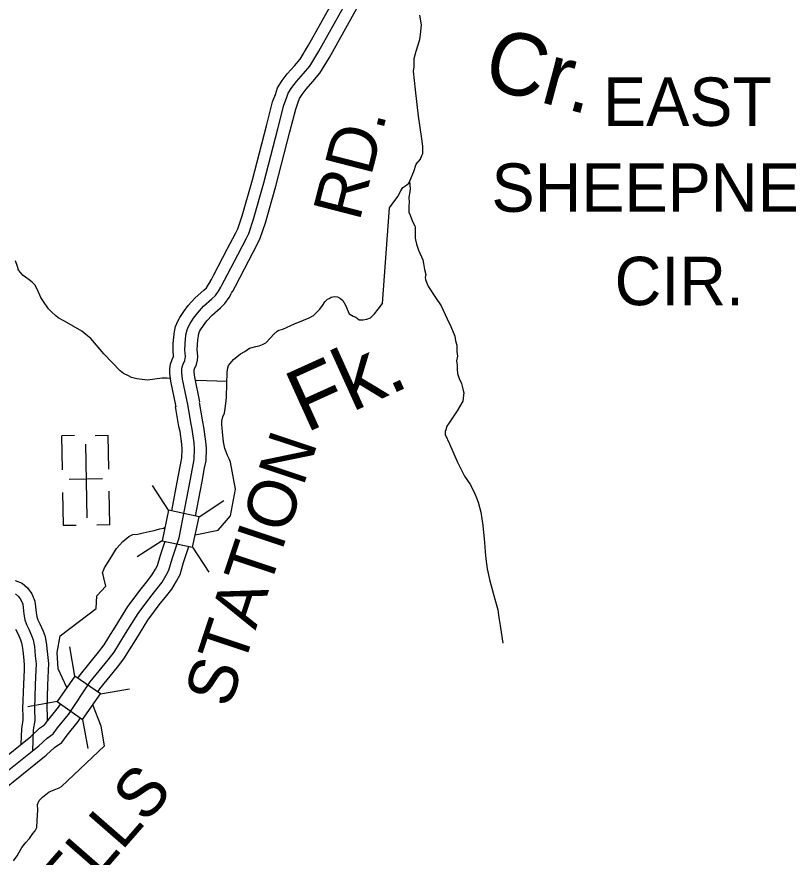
# Model space of a CAD drawing. Extents: x 1551132 to 1791609, y 378168 to 563823.
# Drawn here: x 1676283 to 1682181, y 408888 to 415309 of the extents above; entities that cross this region are included whole.
import ezdxf

# ---------------------------------------------------------------- set-up
doc = ezdxf.new("R2010")
doc.units = 0
for name, color, linetype in [('DESIGN - DRAINAGE - Bridges and Cross Drains Size Text', 7, 'Continuous'), ('DESIGN - ROW - Right-of-Way and Easement Labels', 7, 'Continuous'), ('DESIGN - TRANSPORTATION - Text', 7, 'Continuous'), ('DESIGN - UTILITIES - Cable (Underground) with Text', 7, 'Continuous'), ('SURVEY - DRAINAGE - Storm Sewer', 7, 'Continuous'), ('SURVEY - PROPERTY - Owners', 7, 'Continuous')]:
    doc.layers.add(name, color=color, linetype=linetype)

msp = doc.modelspace()

# ---------------------------------------------------------------- linework, layer by layer
at = {"layer": 'DESIGN - TRANSPORTATION - Text'}
for points in [[(1679132.129, 413849.758), (1679153.645, 413877.808), (1679196.303, 413935.402), (1679218.794, 413979.211), (1679233.085, 414005.078), (1679265.326, 414024.737), (1679279.484, 414038.596), (1679289.734, 414060.505), (1679318.467, 414126.273), (1679337.099, 414184.141), (1679369.532, 414221.826), (1679379.849, 414249.752), (1679386.023, 414265.702), (1679388.24, 414285.703), (1679386.623, 414321.778), (1679377.39, 414393.997), (1679353.049, 414550.526), (1679331.183, 414751.09), (1679316.7, 414893.477), (1679321.067, 414927.478), (1679319.734, 414989.588), (1679336.35, 415045.481), (1679363.341, 415135.308), (1679369.749, 415173.293), (1679376.549, 415247.328), (1679363.341, 415321.596)], [(1679286.092, 414052.721), (1679290.767, 413995.07), (1679286.492, 413971.094), (1679280.026, 413931.118), (1679281.534, 413889.042), (1679281.251, 413865.016), (1679280.859, 413830.982), (1679280.692, 413816.965), (1679290.417, 413792.815), (1679307.858, 413744.53), (1679325.491, 413712.271), (1679327.374, 413702.237), (1679328.958, 413666.17), (1679328.391, 413618.11), (1679332.258, 413606.051), (1679337.857, 413571.934), (1679353.324, 413525.683), (1679386.498, 413453.181), (1679392.148, 413423.071), (1679399.631, 413378.92), (1679409.197, 413340.753), (1679404.914, 413316.777), (1679408.747, 413302.71), (1679418.422, 413274.551), (1679430.105, 413246.375), (1679483.154, 413163.615), (1679528.444, 413100.971), (1679573.31, 413002.286), (1679600.634, 412943.876), (1679631.784, 412869.39), (1679637.367, 412833.281), (1679646.992, 412801.114), (1679646.408, 412751.054), (1679652.016, 412716.945), (1679645.592, 412680.977), (1679649.2, 412646.885), (1679650.85, 412616.825), (1679652.475, 412584.766), (1679666.033, 412546.549), (1679681.574, 412506.306), (1679693.107, 412466.113), (1679694.965, 412454.071), (1679700.757, 412435.979), (1679698.548, 412417.979), (1679694.015, 412371.977), (1679649.141, 412298.434), (1679608.409, 412236.857), (1679588.059, 412207.065), (1679569.751, 412181.256), (1679563.418, 412153.297), (1679557.277, 412141.363), (1679557.002, 412117.329), (1679590.192, 412046.827), (1679650.641, 411911.907), (1679705.348, 411799.087), (1679750.589, 411732.444), (1679783.796, 411663.942), (1679797.454, 411633.733), (1679811.054, 411599.524), (1679830.195, 411525.188), (1679847.011, 411422.844), (1679857.503, 411292.549), (1679862.661, 411220.389), (1679870.061, 411168.229), (1679879.169, 411092.019), (1679896.218, 411009.7), (1679925.009, 410905.206), (1679959.525, 410776.61), (1679968.85, 410718.426), (1679978.158, 410658.232), (1679998.599, 410523.804)], [(1677856.466, 412136.004), (1677853.95, 412165.521), (1677850.267, 412195.605), (1677850.525, 412219.639), (1677858.9, 412253.598), (1677871.183, 412279.491), (1677875.574, 412315.5), (1677882.008, 412355.484), (1677886.491, 412399.502), (1677889.649, 412507.63), (1677890.508, 412587.74), (1677892.833, 412617.766), (1677901.141, 412645.709), (1677939.665, 412691.327), (1677994.164, 412732.761), (1678026.404, 412752.412), (1678062.687, 412776.029), (1678110.877, 412789.488), (1678134.96, 412795.213), (1678161.085, 412804.921), (1678187.259, 412818.638), (1678221.692, 412856.298), (1678248.016, 412884.032), (1678272.265, 412905.782), (1678286.39, 412915.633), (1678316.498, 412923.291), (1678407.021, 412964.301), (1678475.369, 412991.543), (1678517.593, 413009.085), (1678551.817, 413026.711), (1678600.391, 413076.22), (1678620.691, 413102.021), (1678636.999, 413129.88), (1678659.256, 413151.647), (1678671.331, 413157.522), (1678687.448, 413167.348), (1678711.514, 413171.073), (1678735.505, 413168.789), (1678757.396, 413156.514), (1678775.254, 413142.28), (1678794.887, 413105.996), (1678824.194, 413039.553), (1678854.027, 413021.177), (1678875.96, 413012.91), (1678899.759, 412992.602), (1678931.808, 412994.227), (1678959.874, 412997.91), (1678986.024, 413009.619), (1679016.365, 413039.311), (1679044.781, 413075.037), (1679078.497, 413118.997), (1679132.129, 413849.758)], [(1677456.051, 412544.456), (1677429.293, 412548.139), (1677393.286, 412548.581), (1677283.055, 412531.922), (1677201.157, 412542.939), (1677159.258, 412553.473), (1677137.4, 412565.756), (1677097.601, 412584.273), (1677071.827, 412604.615), (1676949.296, 412734.302), (1676848.632, 412851.697), (1676810.966, 412882.198), (1676779.242, 412906.623), (1676646.079, 412982.367), (1676598.371, 413008.984), (1676580.53, 413023.226), (1676546.881, 413053.677), (1676525.156, 413077.978), (1676487.774, 413132.512), (1676466.141, 413164.822), (1676440.817, 413223.206), (1676419.251, 413261.524), (1676399.484, 413281.8), (1676377.685, 413300.092), (1676347.894, 413318.484), (1676330.053, 413332.718), (1676296.512, 413373.185), (1676288.837, 413401.319), (1676273.321, 413443.562)], [(1677889.816, 412522.939), (1677655.271, 412529.039)], [(1677646.663, 411351.541), (1677821.1, 411385.667), (1677916.215, 411495.07), (1677954.256, 411699.617), (1677916.215, 411906.539), (1677905.49, 411932.557), (1677893.74, 411956.732), (1677884.032, 411984.891), (1677874.308, 412011.042), (1677862.833, 412061.252), (1677856.466, 412136.004)], [(1676666.077, 410184.977), (1676600.12, 410327.247), (1676590.612, 410450.925), (1676614.386, 410579.354), (1676890.205, 410788.651), (1676894.963, 410883.787), (1676962.345, 410958.855), (1676947.029, 411023.132), (1676943.262, 411045.208), (1676937.429, 411061.308), (1676953.845, 411099.167), (1677008.861, 411188.67), (1677045.51, 411246.33), (1677092.126, 411299.865), (1677138.566, 411337.382), (1677170.765, 411353.033), (1677206.84, 411356.616), (1677248.98, 411366.141), (1677295.121, 411375.617), (1677333.237, 411383.183), (1677377.419, 411396.692), (1677403.502, 411402.392), (1677415.976, 411408.459)], [(1676258.569, 408859.442), (1676285.002, 408897.193), (1676321.734, 408962.861), (1676352.167, 409000.562), (1676380.516, 409030.279), (1676404.941, 409068.055), (1676423.19, 409089.873), (1676435.482, 409115.773), (1676438.04, 409167.825), (1676442.906, 409247.885), (1676440.748, 409290.611), (1676453.706, 409321.879), (1676466.564, 409334.246), (1676479.922, 409346.713), (1676530.479, 409387.081), (1676606.878, 409418.24), (1676624.569, 409428.782), (1676952.028, 409737.398), (1676928.245, 409889.619), (1676863.172, 410052.198)]]:
    msp.add_lwpolyline(points, dxfattribs=at)
at = {"layer": 'DESIGN - UTILITIES - Cable (Underground) with Text'}
for p, q in [((1676625.12, 412107.223), (1676629.698, 411846.434)), ((1676724.78, 412108.991), (1676625.736, 412107.223)), ((1676981.528, 412109.519), (1676881.776, 412107.759)), ((1676985.931, 411852.771), (1676981.436, 412109.519)), ((1676937.181, 411777.527), (1676683.6, 411773.083)), ((1676632.692, 411675.53), (1676637.053, 411424.107)), ((1676993.37, 411426.361), (1676988.833, 411684.426)), ((1676637.186, 411424.107), (1676735.439, 411425.825)), ((1676993.195, 411426.361), (1676893.709, 411424.594))]:
    msp.add_line(p, q, dxfattribs=at)
msp.add_lwpolyline([(1676807.191, 412042.99), (1676817.057, 411480.036)], dxfattribs=at)
at = {"layer": 'SURVEY - DRAINAGE - Storm Sewer'}
for p, q in [((1677443.403, 411538.149), (1677319.69, 411728.629)), ((1677675.83, 411488.754), (1677866.302, 411612.443)), ((1677394.009, 411305.73), (1677203.536, 411182.033)), ((1677626.369, 411256.344), (1677750.082, 411065.872)), ((1676726.695, 410271.557), (1676687.306, 410495.207)), ((1676921.316, 410135.204), (1677144.99, 410174.684)), ((1676590.425, 410076.912), (1676366.75, 410037.456)), ((1676785.037, 409940.633), (1676824.501, 409716.984))]:
    msp.add_line(p, q, dxfattribs=at)
for points in [[(1677394.009, 411305.73), (1677626.436, 411256.328), (1677675.83, 411488.754), (1677443.403, 411538.149)], [(1676785.037, 409940.633), (1676921.341, 410135.245), (1676726.695, 410271.557), (1676590.425, 410076.912)]]:
    msp.add_lwpolyline(points, close=True, dxfattribs=at)
at = {"layer": 'SURVEY - PROPERTY - Owners'}
for points in [[(1677762.178, 413286.317), (1677770.144, 413301.234), (1677790.127, 413338.393), (1677892.05, 413533.007), (1677956.84, 413657.244), (1677972.306, 413689.036), (1678006.897, 413789.247), (1678084.962, 414063.254), (1678191.185, 414475.457), (1678238.425, 414660.17), (1678259.867, 414716.213), (1678275.191, 414765.381), (1678312.274, 414822.308), (1678350.831, 414873.309), (1678405.163, 414934.652), (1678448.654, 414986.062), (1678513.369, 415091.948), (1678700.732, 415427.541), (1678872.111, 415714.523)], [(1677925.365, 413199.165), (1677933.215, 413213.857), (1677953.54, 413251.675), (1678056.004, 413447.313), (1678122.053, 413573.975), (1678143.535, 413618.109), (1678183.426, 413733.671), (1678263.516, 414014.82), (1678370.372, 414429.447), (1678415.013, 414604.01), (1678434.737, 414655.57), (1678444.179, 414685.871), (1678463.745, 414715.897), (1678494.069, 414756.014), (1678545.035, 414813.558), (1678599.084, 414877.434), (1678673.115, 414998.571), (1678861.32, 415335.68), (1679022.066, 415624.104)], [(1677842.192, 413243.583), (1677850.1, 413258.391), (1677870.25, 413295.876), (1677972.439, 413490.989), (1678037.846, 413616.418), (1678056.263, 413654.26), (1678093.453, 413761.996), (1678172.51, 414039.504), (1678279.041, 414452.898), (1678325.007, 414632.636), (1678345.606, 414686.479), (1678358.048, 414726.397), (1678386.539, 414770.131), (1678421.063, 414815.799), (1678473.745, 414875.276), (1678522.411, 414932.802), (1678591.692, 415046.164), (1678779.471, 415382.498)], [(1677501.15, 412328.433), (1677460.301, 412525.414), (1677453.743, 412582.89), (1677453.801, 412620.066), (1677458.276, 412655.95), (1677471.209, 412690.335), (1677480.909, 412712.319), (1677477.659, 412761.636), (1677478.209, 412812.654), (1677482.442, 412861.389), (1677488.434, 412904.582), (1677497.234, 412943.566), (1677512.992, 412982.342), (1677528.983, 413012.068), (1677558.982, 413058.336), (1677593.89, 413103.837), (1677646.705, 413162.23), (1677712.612, 413219.315), (1677732.087, 413239.299), (1677749.311, 413262.591), (1677762.469, 413286.842)], [(1677589.964, 412346.851), (1677549.957, 412539.797), (1677544.457, 412587.982), (1677544.499, 412614.358), (1677546.957, 412634.066), (1677555.215, 412656.025), (1677567.54, 412683.951), (1677571.123, 412698.51), (1677571.757, 412713.194), (1677568.399, 412764.137), (1677568.874, 412808.238), (1677572.607, 412851.222), (1677577.757, 412888.332), (1677584.073, 412916.324), (1677595.181, 412943.666), (1677607.106, 412965.825), (1677633.13, 413005.968), (1677663.621, 413045.702), (1677710.27, 413097.279), (1677774.902, 413153.264), (1677801.352, 413180.414), (1677826.009, 413213.757), (1677842.192, 413243.583)], [(1677682.287, 412365.993), (1677643.155, 412554.748), (1677638.755, 412593.274), (1677638.78, 412608.424), (1677639.138, 412611.316), (1677642.538, 412620.366), (1677657.13, 412653.417), (1677664.921, 412685.076), (1677666.18, 412714.269), (1677662.721, 412766.737), (1677663.121, 412803.646), (1677666.33, 412840.655), (1677670.604, 412871.439), (1677674.346, 412888.007), (1677680.621, 412903.457), (1677688.312, 412917.757), (1677710.212, 412951.533), (1677736.103, 412985.276), (1677776.344, 413029.769), (1677839.651, 413084.603), (1677873.358, 413119.196), (1677905.741, 413162.989), (1677925.065, 413198.615)], [(1676196.362, 409533.584), (1676450.79, 409738.94), (1676515.488, 409798.275), (1676561.871, 409829.784), (1676594.387, 409875.477), (1676677.568, 409978.663), (1676844.389, 410227.103), (1676980.319, 410395.774), (1677027.002, 410455.326), (1677114.591, 410596.521), (1677210.323, 410749.642), (1677307.82, 410880.704), (1677393.043, 410987.881), (1677425.651, 411041.583), (1677446.101, 411081.401), (1677471.042, 411167.245), (1677524.824, 411328.865), (1677609.705, 411776.569), (1677639.446, 411927.206), (1677642.23, 412008.55), (1677638.722, 412054.66), (1677623.805, 412156.996), (1677614.747, 412197.638), (1677589.964, 412346.851)], [(1677467.55, 411532.979), (1677517.133, 411794.486), (1677537.499, 411897.664), (1677545.474, 411938.023), (1677547.815, 412006.583), (1677544.949, 412044.268), (1677531.007, 412139.912), (1677522.158, 412179.646), (1677496.95, 412331.4)], [(1677648.554, 411494.52), (1677698.762, 411759.335), (1677718.995, 411861.821), (1677729.853, 411916.798), (1677733.053, 412010.442), (1677728.928, 412064.652), (1677713.078, 412173.429), (1677703.82, 412214.947), (1677679.446, 412361.718)], [(1676749.791, 410255.37), (1676768.399, 410283.079), (1676906.505, 410454.45), (1676949.604, 410509.427), (1676986.311, 410568.604), (1677034.552, 410646.372), (1677132.399, 410802.868), (1677233.072, 410938.205), (1677274.305, 410990.048), (1677315.537, 411041.908), (1677343.311, 411087.651), (1677358.086, 411116.418), (1677381.002, 411195.295), (1677416.293, 411301.356)], [(1676901.346, 410149.217), (1676917.487, 410173.251), (1677051.326, 410339.331), (1677101.458, 410403.274), (1677143.516, 410471.076), (1677191.59, 410548.561), (1677285.287, 410698.44), (1677379.727, 410825.385), (1677419.101, 410874.903), (1677467.6, 410935.905), (1677504.857, 410997.265), (1677530.774, 411047.716), (1677557.656, 411140.261), (1677598.439, 411262.814)], [(1676270.786, 411001.548), (1676322.443, 410981.989), (1676364.526, 410944.838), (1676397.567, 410900.837), (1676420.433, 410843.544), (1676430.766, 410757.783), (1676436.732, 410724.499), (1676444.049, 410701.715), (1676459.682, 410671.356), (1676483.531, 410615.488), (1676498.814, 410573.337), (1676510.322, 410509.768), (1676513.114, 410482.726), (1676518.022, 410435.183), (1676523.813, 410367.69), (1676523.238, 410313.363), (1676517.997, 410202.219), (1676512.139, 410021.814), (1676513.655, 409976.913), (1676515.347, 409926.586)], [(1676272.953, 410899.904), (1676294.911, 410880.52), (1676314.644, 410854.244), (1676328.293, 410820.035), (1676337.476, 410743.808), (1676345.034, 410701.657), (1676356.659, 410665.464), (1676374.3, 410631.205), (1676395.783, 410580.879), (1676407.45, 410548.694), (1676416.899, 410496.501), (1676424.149, 410426.308), (1676429.482, 410364.148), (1676428.974, 410316.08), (1676423.782, 410205.969), (1676417.799, 410021.756), (1676420.832, 409931.586), (1676408.049, 409859.618), (1676401.674, 409699.297)], [(1676272.586, 410630.596), (1676292.161, 410592.579), (1676311.368, 410547.586), (1676319.56, 410524.985), (1676327.026, 410483.743), (1676329.101, 410463.717), (1676333.843, 410417.774), (1676338.734, 410360.739), (1676338.293, 410318.697), (1676333.143, 410209.577), (1676327.043, 410021.705), (1676328.759, 409970.696), (1676329.859, 409938.07), (1676317.66, 409869.401), (1676312.96, 409751.182)], [(1676027.591, 409398.206), (1676037.249, 409466.432), (1676055.182, 409518.359), (1676092.19, 409568.968), (1676136.297, 409606.278), (1676389.241, 409810.433), (1676456.823, 409872.41), (1676494.872, 409898.261), (1676519.205, 409932.453), (1676601.578, 410034.639), (1676617.361, 410058.14)], [(1676210.754, 409372.263), (1676217.928, 409422.873), (1676220.953, 409431.64), (1676228.495, 409441.957), (1676254.144, 409463.649), (1676506.88, 409667.646), (1676510.03, 409670.188), (1676571.92, 409726.956), (1676626.319, 409763.907), (1676666.71, 409820.667), (1676750.666, 409924.811), (1676768.949, 409952.046)]]:
    msp.add_lwpolyline(points, dxfattribs=at)

# ---------------------------------------------------------------- texts
at = {"layer": 'DESIGN - DRAINAGE - Bridges and Cross Drains Size Text'}
for s, height, rotation, p in [('Cr.', 474.9903, 345.021025, (1679829.491, 414778.705)), ('Fk.', 474.9931, 24.3718833, (1678492.712, 412127.342))]:
    msp.add_text(s, height=height, rotation=rotation, dxfattribs=at).set_placement(p)
at = {"layer": 'DESIGN - ROW - Right-of-Way and Easement Labels'}
for s, height, rotation, p in [('EAST', 369.9913, 0.0000278, (1680764.425, 414475.333)), ('RD.', 370.0087, 75.5484472, (1678901.886, 413739)), ('SHEEPNECK', 369.9913, 0.0000278, (1679911.819, 413818.874)), ('CIR.', 369.9913, 0.0000278, (1680853.197, 413105.322)), ('STATION', 370.008, 71.5918139, (1677908.19, 410017.962)), ('CAMPBELLS', 370.002, 48.9053167, (1675530.749, 407149.308))]:
    msp.add_text(s, height=height, rotation=rotation, dxfattribs=at).set_placement(p)

doc.saveas('drawing.dxf')
